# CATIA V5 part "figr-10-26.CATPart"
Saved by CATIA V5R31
Part number: Part1
Bounding box of the stored display mesh (mm): x -65.919 to 25.581, y -200.404 to 0.194, z 0 to 71.635
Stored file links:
  D:\PROJECTS\Project 2021\US EDITION\CATIA V5 6R 2021\Resources\Part Files\c10_catia_v5_6r2021_prt\c10_catia_v5_6r2021_prt\figr-10-26.CATPart
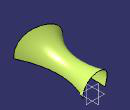
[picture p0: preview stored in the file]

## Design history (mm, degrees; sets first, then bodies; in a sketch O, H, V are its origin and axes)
Set1
  Sketch1 on xy-plane, origin (0, 0, 0), H (1, 0, 0), V (0, 1, 0)
    spline S1 through (-36.6295, 0) (-39.5961, -76.7629) (-56.6868, -154.7631) (-92.5015, -194.2587)
    point P1 (-36.6295, 0)
    coincidence: P1 H
  Sketch2 on xy-plane, origin (0, 0, 0), H (1, 0, 0), V (0, 1, 0)
    spline S1 through (25.5807, 0) (5.5021, -50.6307) (25.5807, -200.404)
    point P1 (25.5807, 0)
    coincidence: P1 H
  Sketch3 on zx-plane, origin (0, 0, 0), H (-1, 0, 0), V (0, 0, 1)
    spline S1 through (-25.5807, 0) (16.4189, 47.2175) (28.9802, 46.33) (36.6295, 0)
    reference projected point E1 (36.6295, 0) from vertex of Sketch1
    reference projected point E2 (-25.5807, 0) from vertex of Sketch2
    point P1 (-25.5807, 0)
    point P2 (36.6295, 0)
    coincidence: P1 H, P2 H, E1 P2, P1 E2
  Sweep1: type Unspec, Profile Sketch3, Guide (Sketch1; Sketch2), FittingPoints (vertex of Sketch1; vertex of Sketch2)
Body1 (main body)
